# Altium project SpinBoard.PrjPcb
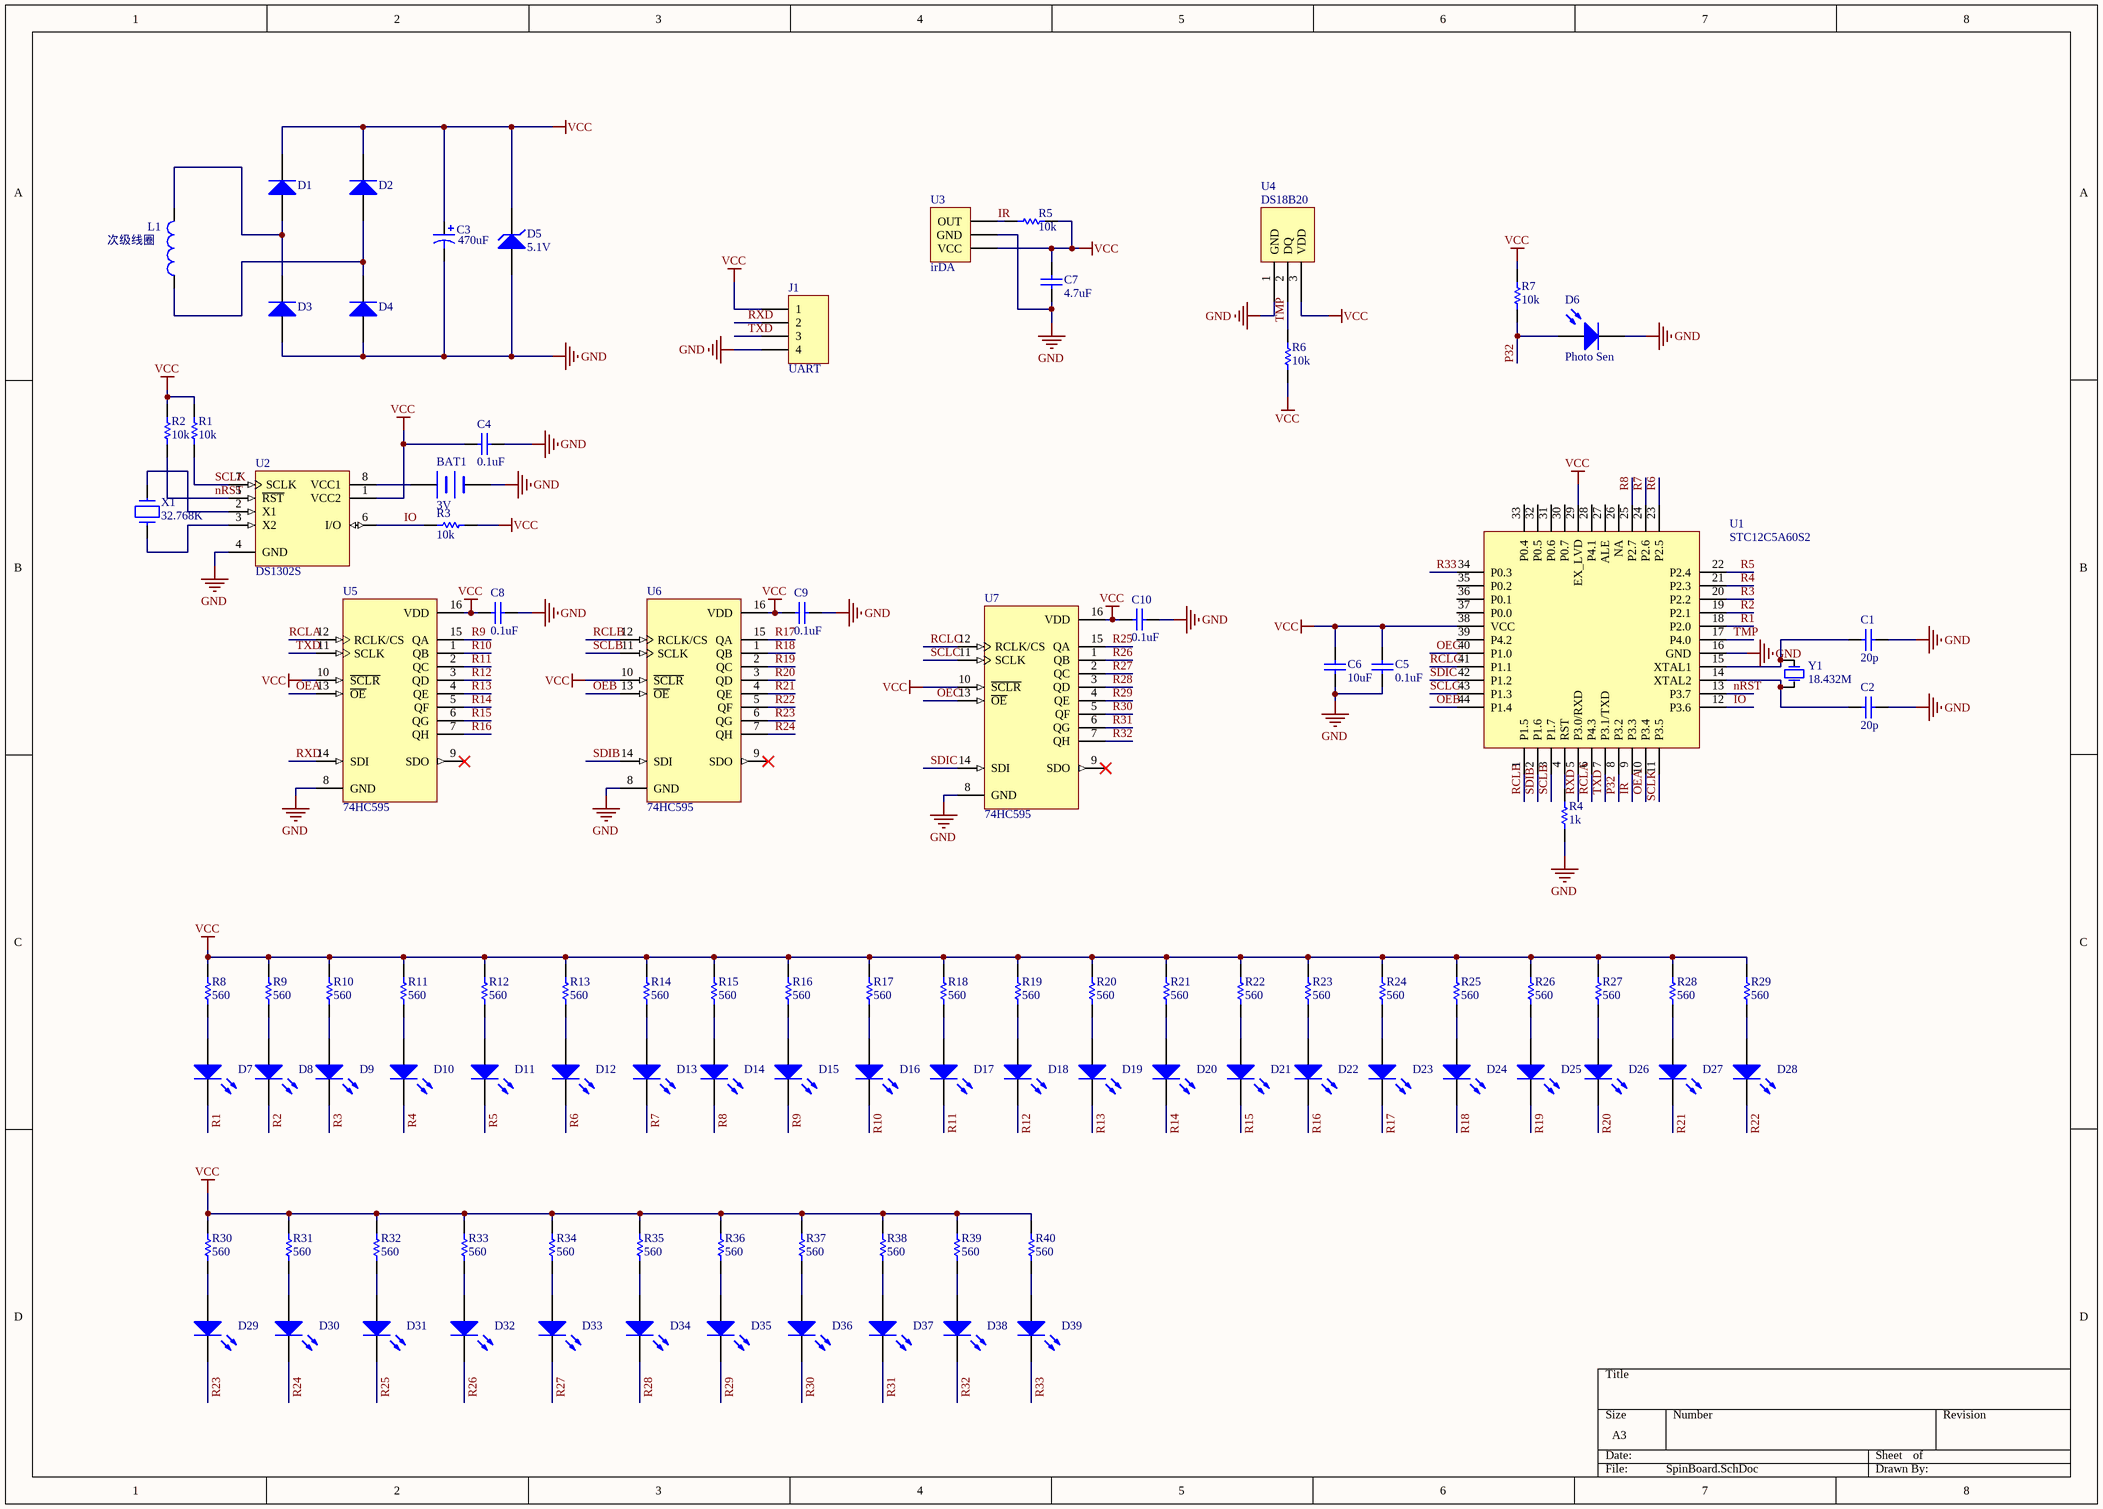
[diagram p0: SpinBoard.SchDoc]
1 sheet, 101 parts. Net scope: global (net labels, ports and power ports of the same name join across sheets).
Board file: SpinBoard.PcbDoc

## Sheet SpinBoard.SchDoc
size A3

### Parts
BAT1  3V  [CR1220-2]
C1  20p  [0603]
C2  20p  [0603]
C3  value 470uF  [C-RB-SD6]  (hidden comment: Cap Pol1)
C4  0.1uF  [0603]
C5  0.1uF  [0603]
C6  10uF  [0603]
C7  4.7uF  [0603]
C8  0.1uF  [0603]
C9  0.1uF  [0603]
C10  0.1uF  [0603]
D1  Diode  [LL34]  (value not drawn)
D2  Diode  [LL34]  (value not drawn)
D3  Diode  [LL34]  (value not drawn)
D4  Diode  [LL34]  (value not drawn)
D5  5.1V  [LL34]
D6  Photo Sen  [LED-3mm]
D7  IR Receiver  [CD1608-0603]  (value not drawn)
D8  IR Receiver  [CD1608-0603]  (value not drawn)
D9  IR Receiver  [CD1608-0603]  (value not drawn)
D10  IR Receiver  [CD1608-0603]  (value not drawn)
D11  IR Receiver  [CD1608-0603]  (value not drawn)
D12  IR Receiver  [CD1608-0603]  (value not drawn)
D13  IR Receiver  [CD1608-0603]  (value not drawn)
D14  IR Receiver  [CD1608-0603]  (value not drawn)
D15  IR Receiver  [CD1608-0603]  (value not drawn)
D16  IR Receiver  [CD1608-0603]  (value not drawn)
D17  IR Receiver  [CD1608-0603]  (value not drawn)
D18  IR Receiver  [CD1608-0603]  (value not drawn)
D19  IR Receiver  [CD1608-0603]  (value not drawn)
D20  IR Receiver  [CD1608-0603]  (value not drawn)
D21  IR Receiver  [CD1608-0603]  (value not drawn)
D22  IR Receiver  [CD1608-0603]  (value not drawn)
D23  IR Receiver  [CD1608-0603]  (value not drawn)
D24  IR Receiver  [CD1608-0603]  (value not drawn)
D25  IR Receiver  [CD1608-0603]  (value not drawn)
D26  IR Receiver  [CD1608-0603]  (value not drawn)
D27  IR Receiver  [CD1608-0603]  (value not drawn)
D28  IR Receiver  [CD1608-0603]  (value not drawn)
D29  IR Receiver  [CD1608-0603]  (value not drawn)
D30  IR Receiver  [CD1608-0603]  (value not drawn)
D31  IR Receiver  [CD1608-0603]  (value not drawn)
D32  IR Receiver  [CD1608-0603]  (value not drawn)
D33  IR Receiver  [CD1608-0603]  (value not drawn)
D34  IR Receiver  [CD1608-0603]  (value not drawn)
D35  IR Receiver  [CD1608-0603]  (value not drawn)
D36  IR Receiver  [CD1608-0603]  (value not drawn)
D37  IR Receiver  [CD1608-0603]  (value not drawn)
D38  IR Receiver  [CD1608-0603]  (value not drawn)
D39  IR Receiver  [CD1608-0603]  (value not drawn)
J1  UART  [HDR1X4]
L1  次级线圈  [HDR1X2]
R1  10k  [0603]
R2  10k  [0603]
R3  10k  [0603]
R4  1k  [0603]
R5  10k  [0603]
R6  10k  [0603]
R7  10k  [0603]
R8  560  [0603]
R9  560  [0603]
R10  560  [0603]
R11  560  [0603]
R12  560  [0603]
R13  560  [0603]
R14  560  [0603]
R15  560  [0603]
R16  560  [0603]
R17  560  [0603]
R18  560  [0603]
R19  560  [0603]
R20  560  [0603]
R21  560  [0603]
R22  560  [0603]
R23  560  [0603]
R24  560  [0603]
R25  560  [0603]
R26  560  [0603]
R27  560  [0603]
R28  560  [0603]
R29  560  [0603]
R30  560  [0603]
R31  560  [0603]
R32  560  [0603]
R33  560  [0603]
R34  560  [0603]
R35  560  [0603]
R36  560  [0603]
R37  560  [0603]
R38  560  [0603]
R39  560  [0603]
R40  560  [0603]
U1  STC12C5A60S2  [TQFP-44]
U2  DS1302S  [SOIC8WA_N]
U3  irDA  [HDR1X3]
U4  DS18B20  [TO-92A]
U5  74HC595  [SOIC-16]
U6  74HC595  [SOIC-16]
U7  74HC595  [SOIC-16]
X1  32.768K  [XTAL-32k]
Y1  value 18.432M  [X-HC-49S]  (hidden comment: XTAL)

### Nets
GND: BAT1.2(-) C1.2 C2.2 C3.2 C4.2 C5.1 C6.1 C7.1 C8.1 C9.1 C10.1 D3.1(A) D4.1(A) D5.1(A) D6.2(K) J1.4 R4.1 U1.16(GND) U2.4(GND) U3.2(GND) U4.1(GND) U5.8(GND) U6.8(GND) U7.8(GND) X1.3(SHELL)
VCC: C3.1 C4.1 C5.2 C6.2 C7.2 C8.2 C9.2 C10.2 D1.2(K) D2.2(K) D5.2(K) J1.1 R1.2 R2.2 R3.1 R5.2 R6.1 R7.2 R8.2 R9.2 R10.2 R11.2 R12.2 R13.2 R14.2 R15.2 R16.2 R17.2 R18.2 R19.2 R20.2 R21.2 R22.2 R23.2 R24.2 R25.2 R26.2 R27.2 R28.2 R29.2 R30.2 R31.2 R32.2 R33.2 R34.2 R35.2 R36.2 R37.2 R38.2 R39.2 R40.2 U1.29(EX_LVD) U1.38(VCC) U2.1(VCC2) U3.3(VCC) U4.3(VDD) U5.10(~{SCLR}) U5.16(VDD) U6.10(~{SCLR}) U6.16(VDD) U7.10(~{SCLR}) U7.16(VDD)
IO: R3.2 U1.12(P3.6) U2.6(I/O)
IR: R5.1 U1.9(P3.3) U3.1(OUT)
nRST: R2.1 U1.13(P3.7) U2.5(~{RST})
OEA: U1.10(P3.4) U5.13(~{OE})
OEB: U1.44(P1.4) U6.13(~{OE})
OEC: U1.40(P1.0) U7.13(~{OE})
P32: D6.1(A) R7.1 U1.8(P3.2)
R1: D7.2(K) U1.18(P2.0)
R2: D8.2(K) U1.19(P2.1)
R3: D9.2(K) U1.20(P2.2)
R4: D10.2(K) U1.21(P2.3)
R5: D11.2(K) U1.22(P2.4)
R6: D12.2(K) U1.23(P2.5)
R7: D13.2(K) U1.24(P2.6)
R8: D14.2(K) U1.25(P2.7)
R9: D15.2(K) U5.15(QA)
R10: D16.2(K) U5.1(QB)
R11: D17.2(K) U5.2(QC)
R12: D18.2(K) U5.3(QD)
R13: D19.2(K) U5.4(QE)
R14: D20.2(K) U5.5(QF)
R15: D21.2(K) U5.6(QG)
R16: D22.2(K) U5.7(QH)
R17: D23.2(K) U6.15(QA)
R18: D24.2(K) U6.1(QB)
R19: D25.2(K) U6.2(QC)
R20: D26.2(K) U6.3(QD)
R21: D27.2(K) U6.4(QE)
R22: D28.2(K) U6.5(QF)
R23: D29.2(K) U6.6(QG)
R24: D30.2(K) U6.7(QH)
R25: D31.2(K) U7.15(QA)
R26: D32.2(K) U7.1(QB)
R27: D33.2(K) U7.2(QC)
R28: D34.2(K) U7.3(QD)
R29: D35.2(K) U7.4(QE)
R30: D36.2(K) U7.5(QF)
R31: D37.2(K) U7.6(QG)
R32: D38.2(K) U7.7(QH)
R33: D39.2(K) U1.34(P0.3)
RCLA: U1.6(P4.3) U5.12(RCLK/CS)
RCLB: U1.1(P1.5) U6.12(RCLK/CS)
RCLC: U1.41(P1.1) U7.12(RCLK/CS)
RXD: J1.2 U1.5(P3.0/RXD) U5.14(SDI)
SCLB: U1.3(P1.7) U6.11(SCLK)
SCLC: U1.43(P1.3) U7.11(SCLK)
SCLK: R1.1 U1.11(P3.5) U2.7(SCLK)
SDIB: U1.2(P1.6) U6.14(SDI)
SDIC: U1.42(P1.2) U7.14(SDI)
TMP: R6.2 U1.17(P4.0) U4.2(DQ)
TXD: J1.3 U1.7(P3.1/TXD) U5.11(SCLK)
NetBAT1_1: BAT1.1(+) U2.8(VCC1)
NetC1_1: C1.1 U1.15(XTAL1) Y1.2(OSC2)
NetC2_1: C2.1 U1.14(XTAL2) Y1.1(OSC1)
NetD1_1: D1.1(A) D3.2(K) L1.2
NetD2_1: D2.1(A) D4.2(K) L1.1
NetD7_1: D7.1(A) R8.1
NetD8_1: D8.1(A) R9.1
NetD9_1: D9.1(A) R10.1
NetD10_1: D10.1(A) R11.1
NetD11_1: D11.1(A) R12.1
NetD12_1: D12.1(A) R13.1
NetD13_1: D13.1(A) R14.1
NetD14_1: D14.1(A) R15.1
NetD15_1: D15.1(A) R16.1
NetD16_1: D16.1(A) R17.1
NetD17_1: D17.1(A) R18.1
NetD18_1: D18.1(A) R19.1
NetD19_1: D19.1(A) R20.1
NetD20_1: D20.1(A) R21.1
NetD21_1: D21.1(A) R22.1
NetD22_1: D22.1(A) R23.1
NetD23_1: D23.1(A) R24.1
NetD24_1: D24.1(A) R25.1
NetD25_1: D25.1(A) R26.1
NetD26_1: D26.1(A) R27.1
NetD27_1: D27.1(A) R28.1
NetD28_1: D28.1(A) R29.1
NetD29_1: D29.1(A) R30.1
NetD30_1: D30.1(A) R31.1
NetD31_1: D31.1(A) R32.1
NetD32_1: D32.1(A) R33.1
NetD33_1: D33.1(A) R34.1
NetD34_1: D34.1(A) R35.1
NetD35_1: D35.1(A) R36.1
NetD36_1: D36.1(A) R37.1
NetD37_1: D37.1(A) R38.1
NetD38_1: D38.1(A) R39.1
NetD39_1: D39.1(A) R40.1
NetR4_2: R4.2 U1.4(RST)
NetU2_2: U2.2(X1) X1.2
NetU2_3: U2.3(X2) X1.1

Not connected (* = marked no-connect by the designer): U1 26(NA) 27(ALE) 28(P4.1) 30(P0.7) 31(P0.6) 32(P0.5) 33(P0.4) 35(P0.2) 36(P0.1) 37(P0.0) 39(P4.2); U5 9(SDO)*; U6 9(SDO)*; U7 9(SDO)*

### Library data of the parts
BAT1 = BATTERY
C1 C2 C4-C10 = Cap: Capacitor
C3 = Cap Pol1: Polarized Capacitor (Radial)
D1-D4 = Diode: Default Diode
D5 = D Zener: Zener Diode
D6 = Photo Sen: Photosensitive Diode
D7-D39 = LED0: Typical INFRARED GaAs LED
J1 = Header 4: Header, 4-Pin
L1 = Inductor: Code_IEC: 1005; Value: 10mH
R1-R40 = Res1: Resistor
U2 = DS1302S: Trickle Charge Timekeeping Chip
U3 = Header 3: Header, 3-Pin
U4 = DS18B20: 温度传感器
U5-U7 = 74HC595: 移位寄存器; ComponentAvailability: Not for New Design
X1 = CRYSTAL
Y1 = XTAL: 晶振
